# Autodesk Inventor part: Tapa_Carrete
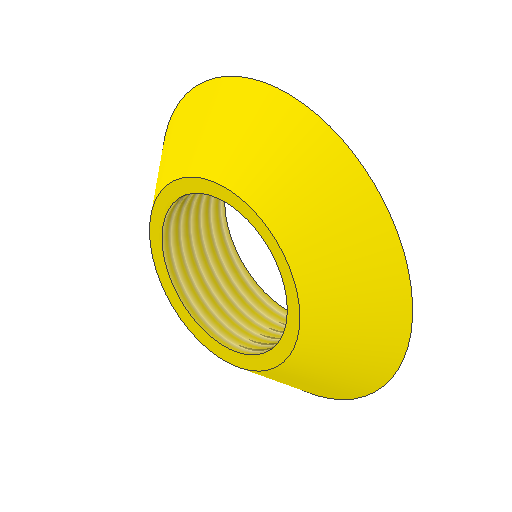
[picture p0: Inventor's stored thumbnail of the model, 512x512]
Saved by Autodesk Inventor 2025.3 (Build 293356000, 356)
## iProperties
Created: 2025-12
Part Number: Tapa_Carrete
Material: Genérico
Document SubType Name: Modeling
Designer: Dell
Density: 1 g/cm^3
Appearance: Valor por defecto
Mass: 79.1943 g
Surface Area: 187.278 cm^2
Volume: 79.1943 cm^3
Author: Dell
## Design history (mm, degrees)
sketch "Boceto1"
  geometry: C1 r 50 at (0, 0); 1 further point
  constraints: 1 centre point, 1 coincident
  dimensions: "d0" = 100 diameter of C1
node "Plano de trabajo1"
sketch "Boceto2"
  geometry: C1 r 30 at (0, 0); 1 further point
  constraints: 1 centre point, 1 coincident
  dimensions: "d2" = 60 diameter of C1
feature "Solevación1" sketch "Boceto2" dims "d3" = 0, "d4" = 90 deg, "d5" = 0, "d6" = 90 deg
sketch "Boceto3"
  geometry: C1 r 25 at (0, 0); 1 further point
  constraints: 1 centre point, 1 coincident
  dimensions: "d7" = 50 diameter of C1
extrude "Extrusión1" cut sketch "Boceto3" distance "d8" = 25; taper "d9" = 0 deg
feature "Rosca1" dims "d10" = 80, "d11" = 0
node "Sólido1"
other parameters: "d1" = 25
